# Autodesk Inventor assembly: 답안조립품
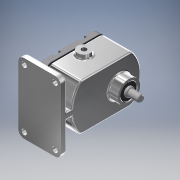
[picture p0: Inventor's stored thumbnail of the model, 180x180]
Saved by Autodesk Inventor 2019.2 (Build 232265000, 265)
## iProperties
Created: 2019-03
Part Number: 답안조립품
Material: 일반
Document SubType Name: Assembly
Designer: User
Author: User
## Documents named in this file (11)
- C:\Users\User\Desktop\490307V1018\답안조립품.iam
- C:\Users\User\Desktop\490307V1018\부품1.ipt
- C:\Users\User\Desktop\490307V1018\개스킷.ipt
- C:\Users\User\Desktop\490307V1018\메인축.ipt
- C:\Users\User\Desktop\490307V1018\베어링부시.ipt
- C:\Users\User\Desktop\490307V1018\볼트 M5.ipt
- C:\Users\User\Desktop\490307V1018\서브축.ipt
- C:\Users\User\Desktop\490307V1018\스퍼기어.ipt
- C:\Users\User\Desktop\490307V1018\오일 실 16 28 7.ipt
- C:\Users\User\Desktop\490307V1018\커버.ipt
- C:\Users\User\Desktop\490307V1018\키 6 x 6 x 18.ipt
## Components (1 placed, 1 different names)
1. 개스킷:1
